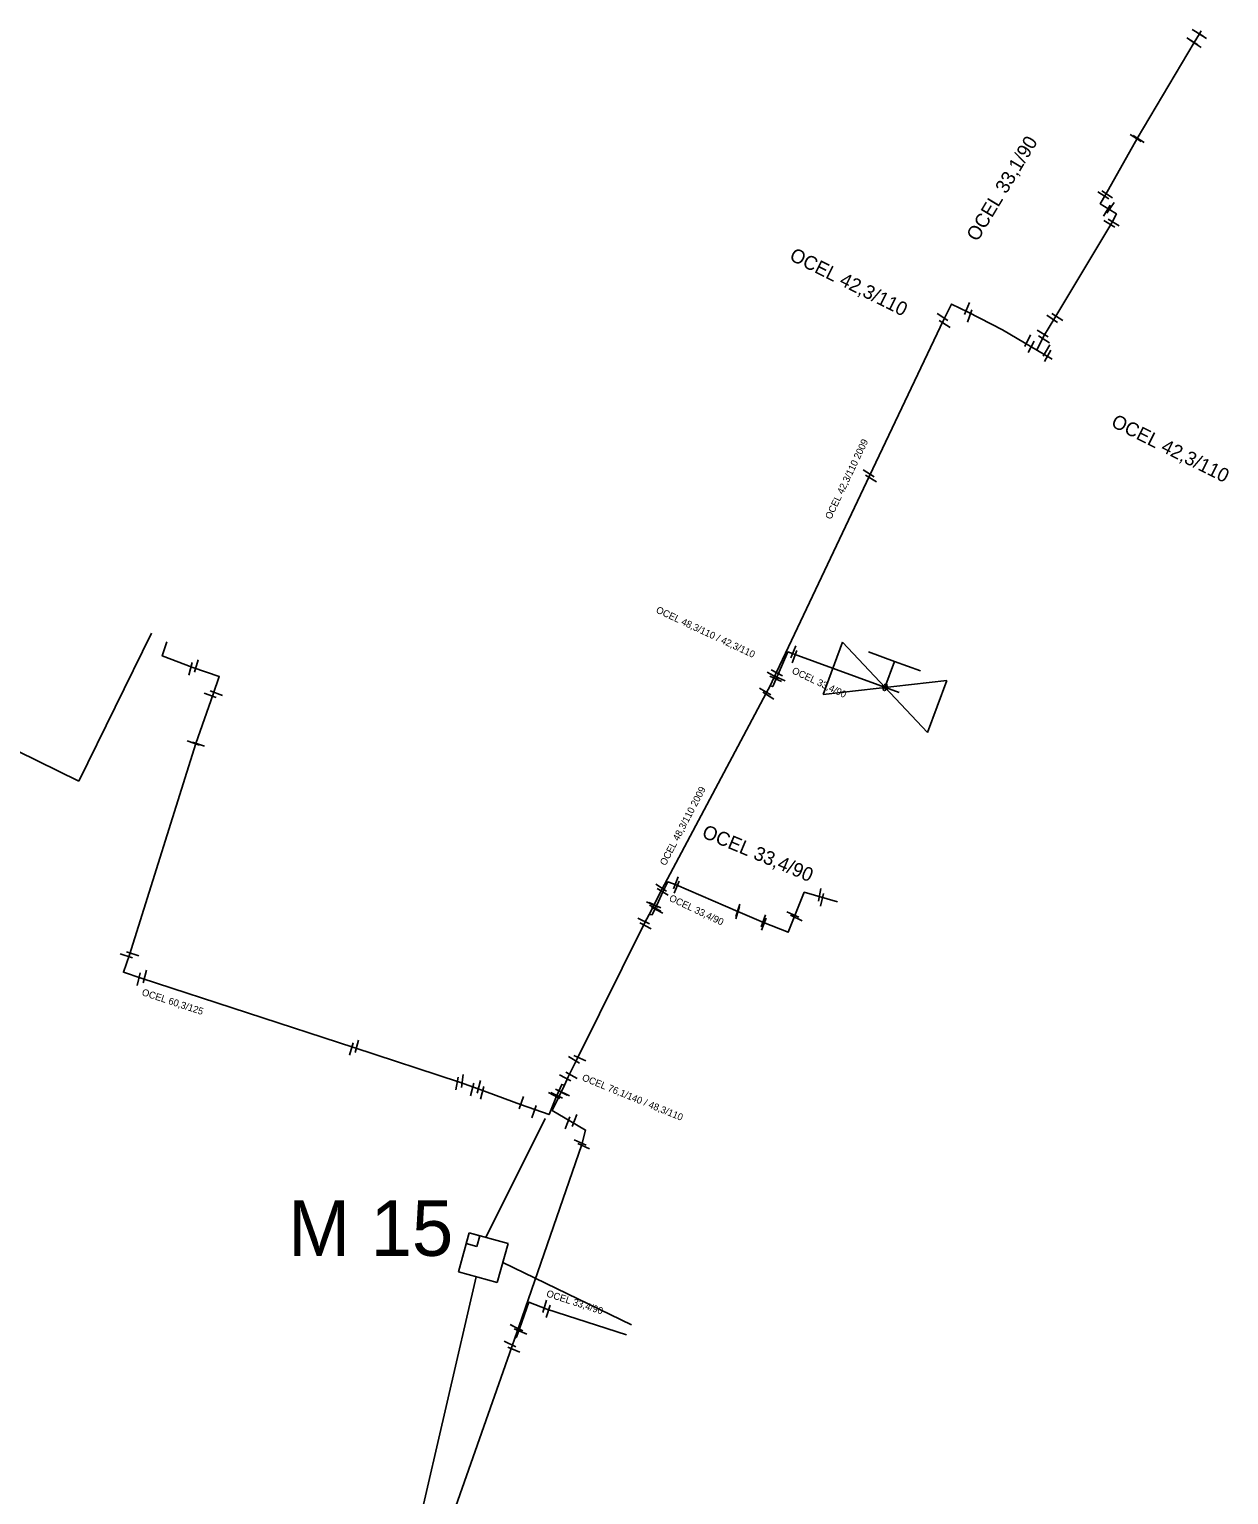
# Model space of a CAD drawing. Extents: x -642943 to -623314, y -1138561 to -1113539.
# Drawn here: x -641921.4 to -641856.7, y -1114900.7 to -1114821.6 of the extents above; entities that cross this region are included whole.
import ezdxf

# ---------------------------------------------------------------- set-up
doc = ezdxf.new("R2010")
doc.units = 0
for name, color, linetype in [('horkovod armatury', 7, 'Continuous'), ('horkovod dimenze', 7, 'Continuous'), ('horkovod předisol', 7, 'Continuous'), ('horkovod sváry', 7, 'Continuous'), ('horkovod trasa', 7, 'Continuous'), ('horkovod zrušený', 7, 'Continuous'), ('horkovod číslo šachty', 7, 'Continuous')]:
    doc.layers.add(name, color=color, linetype=linetype)

# ---------------------------------------------------------------- blocks, each defined once
blk = doc.blocks.new('POINT_DISPLAY')
blk.add_line((0, 0), (0, 0))
blk = doc.blocks.new('SPH_1')
at = {"layer": 'horkovod sváry'}
blk.add_line((0.0001, -0.035), (-0.0001, 0.035), dxfattribs=at)
blk = doc.blocks.new('SPH')
at = {"layer": 'horkovod sváry'}
blk.add_line((0, -0.035), (0, 0.035), dxfattribs=at)
blk = doc.blocks.new('SPH_2')
at = {"layer": 'horkovod sváry'}
blk.add_line((-0.0001, -0.0349), (0.0001, 0.0349), dxfattribs=at)
blk = doc.blocks.new('SCH_01_109')
at = {"layer": 'horkovod armatury'}
for p, q in [((10, 5), (-10, -5)), ((-10, -5), (-10, 5)), ((-10, 5), (10, -5)), ((-5, 5), (0, 5)), ((0, 5), (0, 0)), ((5, 5), (0, 5)), ((10, -5), (10, 5))]:
    blk.add_line(p, q, dxfattribs=at)

msp = doc.modelspace()

# ---------------------------------------------------------------- linework, layer by layer
at = {"layer": 'horkovod armatury'}
for centre in [(-641875.254, -1114857.191), (-641875.188, -1114857.003)]:
    msp.add_circle(centre, 0.075, dxfattribs=at)
at = {"layer": 'horkovod předisol'}
for points in [[(-641867.031, -1114838.881), (-641866.665, -1114838.141), (-641866.053, -1114837.145), (-641862.98, -1114832.02), (-641862.73, -1114831.53), (-641863.142, -1114831.274), (-641863.608, -1114830.985), (-641863.324, -1114830.491), (-641861.606, -1114827.459), (-641858.532, -1114822.278), (-641858.245, -1114821.815), (-641858.151, -1114821.643)], [(-641881.429, -1114857.007), (-641881.09, -1114856.277), (-641876.058, -1114845.67), (-641872.061, -1114837.275), (-641871.638, -1114836.399), (-641870.738, -1114836.835), (-641868.877, -1114837.792), (-641866.199, -1114839.371)], [(-641892.544, -1114878.586), (-641892.689, -1114878.539), (-641892.966, -1114879.177), (-641893.372, -1114880.162), (-641894.145, -1114879.894), (-641894.922, -1114879.622), (-641897.204, -1114878.784), (-641898.213, -1114878.417), (-641903.915, -1114876.541), (-641915.393, -1114872.791), (-641916.363, -1114872.479), (-641916.036, -1114871.542), (-641912.453, -1114860.133), (-641911.515, -1114857.472), (-641911.183, -1114856.515), (-641912.607, -1114856.019), (-641914.265, -1114855.401), (-641914.009, -1114854.633)], [(-641881.429, -1114857.007), (-641881.292, -1114857.057), (-641880.483, -1114855.18), (-641880.13, -1114855.308)], [(-641887.97, -1114869.365), (-641887.274, -1114868.018), (-641881.638, -1114857.416), (-641881.429, -1114857.007)], [(-641887.97, -1114869.365), (-641887.805, -1114869.371), (-641887.543, -1114868.865), (-641887.207, -1114868.109), (-641886.959, -1114867.599), (-641886.502, -1114867.763)], [(-641886.502, -1114867.763), (-641883.181, -1114869.194), (-641881.784, -1114869.792), (-641880.452, -1114870.317), (-641879.59, -1114868.16), (-641877.791, -1114868.685)], [(-641892.544, -1114878.586), (-641892.339, -1114878.13), (-641891.862, -1114877.151), (-641888.212, -1114869.824), (-641887.97, -1114869.365)], [(-641895.219, -1114892.244), (-641895.007, -1114891.626), (-641891.598, -1114881.774), (-641891.397, -1114881.001), (-641892.203, -1114880.538), (-641893.204, -1114879.948), (-641892.544, -1114878.586)], [(-641895.219, -1114892.244), (-641895.13, -1114892.182), (-641894.957, -1114891.682), (-641894.466, -1114890.296), (-641893.497, -1114890.665), (-641889.188, -1114892.054)], [(-641899.345, -1114903.968), (-641895.384, -1114892.707), (-641895.219, -1114892.244)]]:
    msp.add_lwpolyline(points, dxfattribs=at)
at = {"layer": 'horkovod trasa'}
msp.add_line((-641874.47, -1114857.372), (-641880.13, -1114855.308), dxfattribs=at)
for points in [[(-641867.031, -1114838.881), (-641866.665, -1114838.141), (-641866.053, -1114837.145), (-641862.98, -1114832.02), (-641862.73, -1114831.53), (-641863.142, -1114831.274), (-641863.608, -1114830.985), (-641863.324, -1114830.491), (-641861.606, -1114827.459), (-641858.532, -1114822.278), (-641858.245, -1114821.815), (-641858.151, -1114821.643)], [(-641881.429, -1114857.007), (-641881.09, -1114856.277), (-641876.058, -1114845.67), (-641872.061, -1114837.275), (-641871.638, -1114836.399), (-641870.738, -1114836.835), (-641868.877, -1114837.792), (-641866.199, -1114839.371)], [(-641892.544, -1114878.586), (-641892.689, -1114878.539), (-641892.966, -1114879.177), (-641893.372, -1114880.162), (-641894.145, -1114879.894), (-641894.922, -1114879.622), (-641897.204, -1114878.784), (-641898.213, -1114878.417), (-641903.915, -1114876.541), (-641915.393, -1114872.791), (-641916.363, -1114872.479), (-641916.036, -1114871.542), (-641912.453, -1114860.133), (-641911.515, -1114857.472), (-641911.183, -1114856.515), (-641912.607, -1114856.019), (-641914.265, -1114855.401), (-641914.009, -1114854.633)], [(-641881.429, -1114857.007), (-641881.292, -1114857.057), (-641880.483, -1114855.18), (-641880.13, -1114855.308)], [(-641887.97, -1114869.365), (-641887.274, -1114868.018), (-641881.638, -1114857.416), (-641881.429, -1114857.007)], [(-641887.97, -1114869.365), (-641887.805, -1114869.371), (-641887.543, -1114868.865), (-641887.207, -1114868.109), (-641886.959, -1114867.599), (-641886.502, -1114867.763)], [(-641886.502, -1114867.763), (-641883.181, -1114869.194), (-641881.784, -1114869.792), (-641880.452, -1114870.317), (-641879.59, -1114868.16), (-641877.791, -1114868.685)], [(-641892.544, -1114878.586), (-641892.339, -1114878.13), (-641891.862, -1114877.151), (-641888.212, -1114869.824), (-641887.97, -1114869.365)], [(-641895.219, -1114892.244), (-641895.007, -1114891.626), (-641891.598, -1114881.774), (-641891.397, -1114881.001), (-641892.203, -1114880.538), (-641893.204, -1114879.948), (-641892.544, -1114878.586)], [(-641895.219, -1114892.244), (-641895.13, -1114892.182), (-641894.957, -1114891.682), (-641894.466, -1114890.296), (-641893.497, -1114890.665), (-641889.188, -1114892.054)], [(-641899.345, -1114903.968), (-641895.384, -1114892.707), (-641895.219, -1114892.244)]]:
    msp.add_lwpolyline(points, dxfattribs=at)
at = {"layer": 'horkovod zrušený'}
for p, q in [((-641914.846, -1114854.169), (-641918.772, -1114862.156)), ((-641918.772, -1114862.156), (-641922.092, -1114860.524)), ((-641896.779, -1114886.795), (-641893.574, -1114880.384)), ((-641898.269, -1114888.656), (-641897.685, -1114886.545)), ((-641897.685, -1114886.545), (-641897.845, -1114887.123)), ((-641897.107, -1114886.705), (-641897.685, -1114886.545)), ((-641895.584, -1114887.126), (-641897.685, -1114886.545)), ((-641897.267, -1114887.283), (-641897.107, -1114886.705)), ((-641897.845, -1114887.123), (-641897.267, -1114887.283)), ((-641895.584, -1114887.126), (-641896.168, -1114889.237)), ((-641895.87, -1114888.157), (-641888.926, -1114891.518)), ((-641902.074, -1114909.531), (-641897.306, -1114888.923)), ((-641896.168, -1114889.237), (-641898.269, -1114888.656))]:
    msp.add_line(p, q, dxfattribs=at)

# ---------------------------------------------------------------- block references
at = {"layer": 'horkovod armatury', "xscale": 0.29998715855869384, "yscale": 0.2999871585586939, "rotation": -20.07870921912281}
msp.add_blockref('SCH_01_109', (-641875.229, -1114857.1), dxfattribs=at)
at = {"layer": 'horkovod sváry'}
for name, p, xscale, yscale, rotation in [('SPH_1', (-641858.344, -1114821.749), 9.99998734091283, 9.999987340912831, 57.867124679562), ('SPH_1', (-641858.163, -1114821.87), 9.999977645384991, 9.999977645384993, 57.704053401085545), ('SPH', (-641858.63, -1114822.21), 9.999972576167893, 9.999972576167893, 56.02163303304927), ('SPH', (-641858.45, -1114822.34), 10.000004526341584, 10.000004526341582, 56.02947786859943), ('SPH_1', (-641861.69, -1114827.43), 10.000000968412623, 10.00000096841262, 56.75155874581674), ('SPH_1', (-641861.53, -1114827.49), 10.000019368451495, 10.000019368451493, 56.48035051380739), ('SPH_1', (-641863.43, -1114830.52), 9.999971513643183, 9.999971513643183, 57.49895212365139), ('SPH_1', (-641863.23, -1114830.47), 9.99998771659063, 9.999987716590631, 57.70945548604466), ('SPH_1', (-641863.25, -1114831.35), 10.000008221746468, 10.000008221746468, -32.03360786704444), ('SPH', (-641863.05, -1114831.2), 9.99999409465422, 9.999994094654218, -34.154782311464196), ('SPH', (-641863.11, -1114832.07), 9.999989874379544, 9.999989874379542, 58.74669397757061), ('SPH_1', (-641862.88, -1114832), 9.999982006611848, 9.999982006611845, 58.78535860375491), ('SPH', (-641872.124, -1114837.1), 10.000017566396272, 10.000017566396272, 57.75216139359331), ('SPH_1', (-641870.794, -1114836.64), 10.000003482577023, 10.000003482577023, -22.403136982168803), ('SPH_1', (-641870.664, -1114837.04), 10.000011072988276, 10.000011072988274, -19.774375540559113), ('SPH_1', (-641865.92, -1114837.1), 9.999981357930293, 9.999981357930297, 57.83559085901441), ('SPH_1', (-641872.004, -1114837.48), 9.999999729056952, 9.999999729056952, 57.50316758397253), ('SPH_1', (-641866.2, -1114837.2), 9.999985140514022, 9.99998514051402, 56.0702508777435), ('SPH_1', (-641867.53, -1114838.37), 10.000007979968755, 10.000007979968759, -26.316748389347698), ('SPH_1', (-641867.34, -1114838.71), 9.999984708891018, 9.99998470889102, -27.250793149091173), ('SPH', (-641866.71, -1114837.99), 10.000000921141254, 10.000000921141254, 58.16317323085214), ('SPH_1', (-641866.64, -1114838.31), 10.000022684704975, 10.000022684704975, 57.488065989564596), ('SPH_1', (-641866.51, -1114838.91), 10.000010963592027, 10.000010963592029, -30.73904538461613), ('SPH_1', (-641866.45, -1114839.19), 9.999990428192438, 9.999990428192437, -29.407197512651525), ('SPH_1', (-641876.114, -1114845.54), 9.999997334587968, 9.999997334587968, 58.47104823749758), ('SPH_1', (-641875.984, -1114845.82), 9.99999622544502, 9.99999622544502, 58.97209263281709), ('SPH_1', (-641880.184, -1114855.17), 9.999983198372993, 9.999983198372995, -22.237058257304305), ('SPH_1', (-641880.114, -1114855.44), 9.999983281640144, 9.999983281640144, -20.60422876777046), ('SPH_1', (-641912.744, -1114856.1), 9.999997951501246, 9.999997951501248, -15.096183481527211), ('SPH_1', (-641912.424, -1114855.94), 9.999983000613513, 9.999983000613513, -16.67966887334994), ('SPH_2', (-641881.29, -1114856.44), 10.000006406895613, 10.000006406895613, 61.08323445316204), ('SPH_1', (-641881.14, -1114856.64), 10.000023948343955, 10.000023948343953, 64.81989316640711), ('SPH_1', (-641881.074, -1114856.31), 9.999970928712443, 9.999970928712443, 62.55422027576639), ('SPH', (-641880.944, -1114856.6), 10.000005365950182, 10.00000536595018, 65.61447130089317), ('SPH_1', (-641911.674, -1114857.53), 9.999982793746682, 9.999982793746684, 69.73430637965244), ('SPH_1', (-641911.344, -1114857.41), 10.00002218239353, 10.00002218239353, 69.58784922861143), ('SPH_1', (-641881.704, -1114857.32), 10.00000125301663, 10.000001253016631, 59.26992320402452), ('SPH_1', (-641881.534, -1114857.55), 10.00000231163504, 10.000002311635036, 57.823373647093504), ('SPH_1', (-641912.584, -1114860.1), 10.00000478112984, 10.00000478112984, 70.63676060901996), ('SPH_1', (-641912.304, -1114860.16), 10.0000224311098, 10.000022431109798, 70.97241961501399), ('SPH_1', (-641887.314, -1114867.91), 9.999973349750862, 9.999973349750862, 55.869636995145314), ('SPH_1', (-641886.524, -1114867.65), 10.000023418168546, 10.000023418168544, -22.307312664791), ('SPH_1', (-641886.484, -1114867.88), 9.999977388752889, 9.999977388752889, -22.879611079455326), ('SPH_1', (-641887.234, -1114868.14), 10.000015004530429, 10.000015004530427, 58.067073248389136), ('SPH_2', (-641878.76, -1114868.3), 10.000009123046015, 10.000009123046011, -10.69903046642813), ('SPH_2', (-641878.63, -1114868.57), 9.999977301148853, 9.999977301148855, -14.408392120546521), ('SPH_1', (-641887.794, -1114868.82), 10.000010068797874, 10.000010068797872, 64.41054464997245), ('SPH_1', (-641887.654, -1114868.86), 10.000005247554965, 10.000005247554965, 64.45016488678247), ('SPH_1', (-641887.644, -1114869.02), 10.0000004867, 10.0000004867, 61.90963714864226), ('SPH_1', (-641887.534, -1114869.13), 9.999983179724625, 9.999983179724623, 63.16528711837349), ('SPH_2', (-641883.19, -1114869.26), 9.99997784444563, 9.999977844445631, -16.985464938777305), ('SPH_2', (-641883.17, -1114869.13), 9.999998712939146, 9.999998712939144, -17.799874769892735), ('SPH_2', (-641881.8, -1114869.7), 10.00000369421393, 10.00000369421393, -19.22190214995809), ('SPH', (-641880.21, -1114869.36), 10.000015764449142, 10.00001576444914, 65.96174063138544), ('SPH_2', (-641880.02, -1114869.55), 10.00001783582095, 10.00001783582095, 64.71044945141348), ('SPH_1', (-641888.264, -1114869.71), 9.999998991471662, 9.999998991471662, 63.46752283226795), ('SPH_1', (-641888.164, -1114869.97), 10.000012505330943, 10.000012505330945, 61.561313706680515), ('SPH_2', (-641881.77, -1114869.88), 9.999995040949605, 9.999995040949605, -21.734078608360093), ('SPH_1', (-641916.204, -1114871.59), 10.000018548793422, 10.000018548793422, 72.02690250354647), ('SPH', (-641915.854, -1114871.49), 9.999998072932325, 9.999998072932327, 72.60877911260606), ('SPH_1', (-641915.534, -1114872.86), 9.999989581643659, 9.999989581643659, -13.566445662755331), ('SPH_1', (-641915.204, -1114872.71), 9.999978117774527, 9.999978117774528, -16.098990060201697), ('SPH_1', (-641904.047, -1114876.624), 9.99999997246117, 9.99999997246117, -15.957379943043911), ('SPH', (-641903.753, -1114876.478), 9.999989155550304, 9.999989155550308, -14.856467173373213), ('SPH_1', (-641892.024, -1114877.21), 9.999992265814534, 9.999992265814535, 60.005827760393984), ('SPH_1', (-641891.704, -1114877.12), 9.999981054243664, 9.999981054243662, 66.42154125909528), ('SPH', (-641898.054, -1114878.35), 10.000000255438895, 10.000000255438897, -8.638206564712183), ('SPH_1', (-641892.504, -1114878.18), 10.000007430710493, 10.000007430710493, 61.43165852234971), ('SPH_1', (-641892.154, -1114878.05), 10.000002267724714, 10.000002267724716, 61.523347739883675), ('SPH', (-641898.344, -1114878.49), 10.000016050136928, 10.000016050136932, -11.310037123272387), ('SPH_1', (-641897.524, -1114878.81), 9.999989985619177, 9.999989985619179, -13.728159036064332), ('SPH_1', (-641897.164, -1114878.67), 10.00000452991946, 10.00000452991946, -14.620840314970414), ('SPH', (-641896.984, -1114878.99), 9.99998088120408, 9.999980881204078, -13.825418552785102), ('SPH', (-641892.714, -1114878.96), 9.999999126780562, 9.99999912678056, 62.8377478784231), ('SPH_1', (-641892.584, -1114879), 9.999989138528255, 9.999989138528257, 63.1581280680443), ('SPH_1', (-641894.874, -1114879.52), 9.999997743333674, 9.999997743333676, -20.076359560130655), ('SPH_1', (-641894.184, -1114880.01), 9.999983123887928, 9.999983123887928, -20.304946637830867), ('SPH_1', (-641893.094, -1114879.13), 9.999991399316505, 9.999991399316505, 62.410781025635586), ('SPH', (-641892.954, -1114879.12), 10.000018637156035, 10.000018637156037, 63.94492271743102), ('SPH_1', (-641892.374, -1114880.61), 10.000000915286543, 10.00000091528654, -21.26607458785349), ('SPH_1', (-641891.994, -1114880.49), 10.000013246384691, 10.000013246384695, -21.999389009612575), ('SPH_1', (-641891.694, -1114881.68), 9.999997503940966, 9.999997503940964, 65.64754859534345), ('SPH_1', (-641891.504, -1114881.87), 10.000010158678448, 10.000010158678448, 65.49256263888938), ('SPH_1', (-641893.604, -1114890.52), 9.999990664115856, 9.999990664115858, -17.167422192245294), ('SPH_1', (-641893.414, -1114890.79), 9.999990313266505, 9.999990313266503, -18.397488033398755), ('SPH_1', (-641895.164, -1114891.66), 9.999985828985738, 9.999985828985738, 63.13808215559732), ('SPH', (-641895.104, -1114891.69), 10.000011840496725, 10.000011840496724, 65.2377917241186), ('SPH_1', (-641894.934, -1114891.87), 9.999989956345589, 9.999989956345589, 66.07234869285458), ('SPH', (-641894.884, -1114891.89), 9.999997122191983, 9.99999712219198, 66.29226549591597), ('SPH_1', (-641895.484, -1114892.55), 9.999997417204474, 9.999997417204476, 64.5686700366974), ('SPH', (-641895.274, -1114892.86), 9.999989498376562, 9.999989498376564, 68.59841742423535)]:
    msp.add_blockref(name, p, dxfattribs=dict(at, xscale=xscale, yscale=yscale, rotation=rotation))
at = {"layer": 'horkovod zrušený'}
msp.add_blockref('POINT_DISPLAY', (-641897.478, -1114886.92), dxfattribs=at)

# ---------------------------------------------------------------- texts
at = {"layer": 'horkovod dimenze'}
for s, height, rotation, p in [('OCEL 33,1/90', 0.75, 58.9378, (-641870.236, -1114833.065)), ('OCEL 42,3/110', 0.75, 333.43495, (-641880.44, -1114833.991)), ('OCEL 42,3/110', 0.75, 333.43495, (-641863.069, -1114842.979)), ('OCEL 42,3/110 2009', 0.375, 64.62446, (-641878.144, -1114848.058)), ('OCEL 48,3/110 / 42,3/110', 0.375, 334.85815, (-641887.632, -1114853.04)), ('OCEL 33,4/90', 0.375, 334.62446, (-641880.294, -1114856.317)), ('OCEL 48,3/110 2009', 0.375, 62.39082, (-641887.081, -1114866.755)), ('OCEL 33,4/90', 0.75, 337.30621, (-641885.168, -1114865.171)), ('OCEL 33,4/90', 0.375, 334.62446, (-641886.924, -1114868.603)), ('OCEL 60,3/125', 0.37495, 341.79588, (-641915.397, -1114873.712)), ('OCEL 76,1/140 / 48,3/110', 0.375, 337.80526, (-641891.626, -1114878.307)), ('OCEL 33,4/90', 0.375, 341.91751, (-641893.55, -1114889.978))]:
    msp.add_text(s, height=height, rotation=rotation, dxfattribs=at).set_placement(p)
at = {"layer": 'horkovod číslo šachty'}
msp.add_text('M 15', height=3, dxfattribs=at).set_placement((-641907.466, -1114887.794))

doc.saveas('drawing.dxf')
